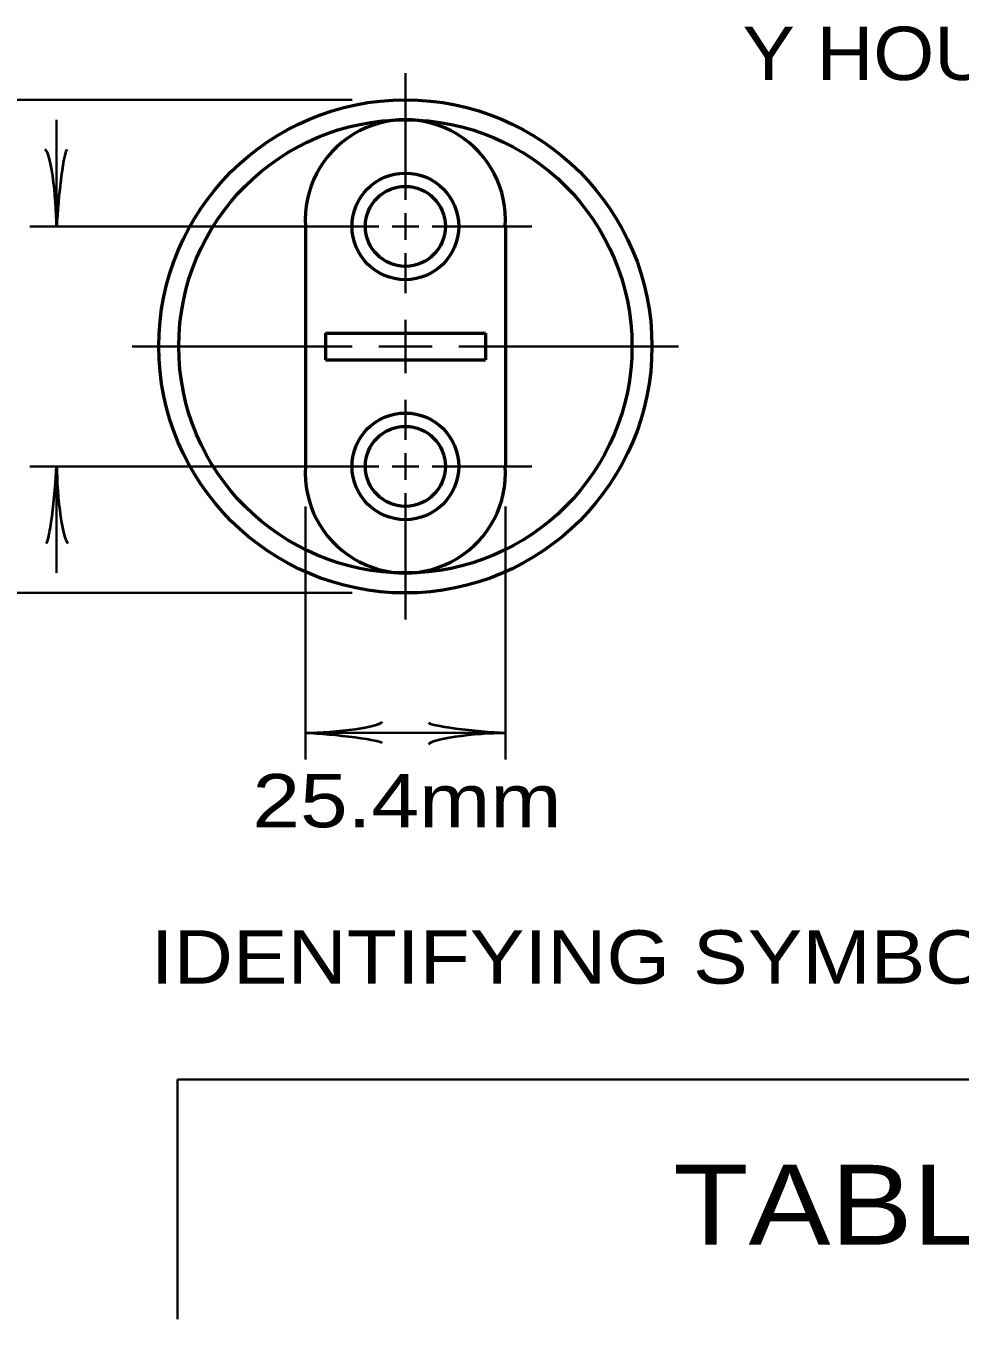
# Model space of a CAD drawing. Extents: x -32 to 824, y -6 to 538.
# Drawn here: x 89 to 131, y 152.1 to 210.3 of the extents above; entities that cross this region are included whole.
import ezdxf

# ---------------------------------------------------------------- set-up
doc = ezdxf.new("R2010")
doc.units = 0
doc.header["$LTSCALE"] = 1.1
doc.layers.add('1', color=7, linetype='Continuous', lineweight=53)

msp = doc.modelspace()

# ---------------------------------------------------------------- linework, layer by layer
at = {"layer": '1', "lineweight": 35}
for p, q in [((106.065, 208.214), (106.065, 202.514)), ((103.665, 207.014), (82.065, 207.014)), ((90.368, 206.114), (90.368, 201.314)), ((106.065, 201.914), (106.065, 200.714)), ((89.168, 201.314), (104.865, 201.314)), ((105.465, 201.314), (106.665, 201.314)), ((107.265, 201.314), (111.765, 201.314)), ((106.065, 200.114), (106.065, 198.314)), ((93.765, 195.914), (103.665, 195.914)), ((108.465, 195.914), (118.365, 195.914)), ((106.065, 193.514), (106.065, 191.714)), ((106.065, 191.114), (106.065, 189.914)), ((89.168, 190.514), (104.865, 190.514)), ((90.368, 190.514), (90.368, 185.714)), ((105.465, 190.514), (106.665, 190.514)), ((107.265, 190.514), (111.765, 190.514)), ((106.065, 189.314), (106.065, 183.614)), ((101.565, 188.714), (101.565, 177.314)), ((110.565, 188.714), (110.565, 177.314)), ((103.665, 184.814), (82.065, 184.814)), ((101.565, 178.514), (110.565, 178.514)), ((146.565, 162.914), (95.814, 162.914)), ((95.814, 162.914), (95.814, 152.132))]:
    msp.add_line(p, q, dxfattribs=at)
at = {"layer": '1'}
for p, q in [((101.565, 201.314), (101.565, 195.914)), ((110.565, 201.314), (110.565, 195.914)), ((102.465, 196.514), (106.065, 196.514)), ((102.465, 196.514), (102.465, 195.314)), ((106.065, 196.514), (109.665, 196.514)), ((109.665, 196.514), (109.665, 195.314)), ((101.565, 195.914), (101.565, 190.514)), ((110.565, 195.914), (110.565, 190.514)), ((102.465, 195.314), (106.065, 195.314)), ((106.065, 195.314), (109.665, 195.314))]:
    msp.add_line(p, q, dxfattribs=at)
at = {"layer": '1', "lineweight": 35}
for points in [[(106.065, 197.114), (106.065, 195.914), (106.065, 194.714)], [(104.865, 195.914), (106.065, 195.914), (107.265, 195.914)]]:
    msp.add_lwpolyline(points, dxfattribs=at)
at = {"layer": '1'}
for centre, radius in [((106.065, 195.914), 11.1), ((106.065, 195.914), 10.2), ((106.065, 201.314), 2.4), ((106.065, 201.314), 1.8), ((106.065, 190.514), 2.4), ((106.065, 190.514), 1.8)]:
    msp.add_circle(centre, radius, dxfattribs=at)
for centre, start, end in [((106.065, 201.605), 356.30478, 183.69522), ((106.065, 190.223), 176.30478, 3.69522)]:
    msp.add_arc(centre, 4.509, start, end, dxfattribs=at)
at = {"layer": '1', "lineweight": 40}
for centre, major_axis, ratio, start_param, end_param in [((90.036, 202.624), (0.187, -2.143), 0.122415, 0.896353, 3.141593), ((90.621, 202.659), (-0.211, -2.108), 0.07063, 3.140715, 5.41811), ((90.114, 189.169), (0.211, 2.108), 0.07063, 3.140715, 5.41811), ((90.699, 189.205), (-0.187, 2.143), 0.122415, 0.896353, 3.141593), ((102.875, 178.846), (-2.143, -0.187), 0.122415, 0.896353, 3.141593), ((102.875, 178.846), (-2.143, -0.187), 0.122415, 0.896353, 3.141593), ((109.221, 178.768), (2.108, -0.211), 0.07063, 3.140715, 5.41811), ((102.91, 178.26), (-2.108, 0.211), 0.07063, 3.140715, 5.41811), ((102.91, 178.26), (-2.108, 0.211), 0.07063, 3.140715, 5.41811), ((109.256, 178.183), (2.143, 0.187), 0.122415, 0.896353, 3.141593)]:
    msp.add_ellipse(centre, major_axis=major_axis, ratio=ratio, start_param=start_param, end_param=end_param, dxfattribs=at)

# ---------------------------------------------------------------- texts
at = {"layer": '1'}
for s, height, width, p in [('Y HOUSING', 2.4, 1.1, (121.242, 207.903)), ('25.4mm', 2.4, 1.2, (99.184, 174.268)), ('IDENTIFYING SYMBOLS IV', 2.4, 1.15, (94.612, 167.234)), ('TABLE X', 3.6, 1.15, (118.13, 155.48))]:
    msp.add_text(s, height=height, dxfattribs=dict(at, width=width)).set_placement(p)

doc.saveas('drawing.dxf')
